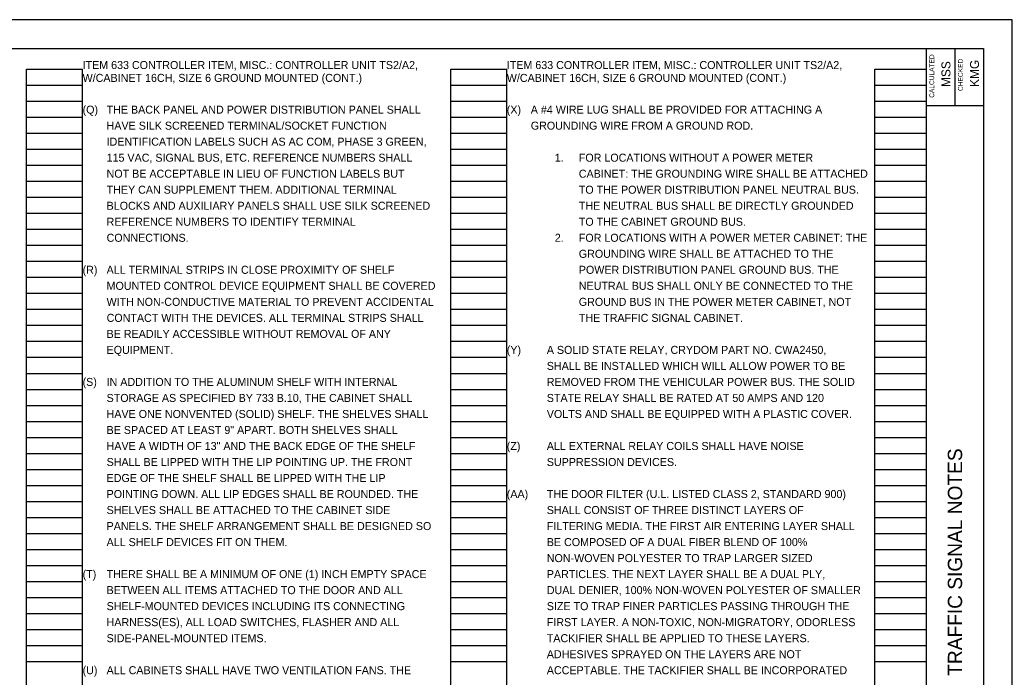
# Model space of a CAD drawing. Extents: x -38 to 65, y -51 to 25.
# Drawn here: x 16.14 to 33.49, y 3 to 14.49 of the extents above; entities that cross this region are included whole.
import ezdxf

# ---------------------------------------------------------------- set-up
doc = ezdxf.new("R2010")
doc.units = 0
for name, color, linetype in [('Level 63', 7, 'Continuous'), ('PF_P_Text', 7, 'Continuous'), ('SC_Scratch1', 7, 'Continuous'), ('SH_Cut_Line', 7, 'Continuous'), ('SH_Data', 7, 'Continuous'), ('SH_Text', 7, 'Continuous')]:
    doc.layers.add(name, color=color, linetype=linetype)

msp = doc.modelspace()

# ---------------------------------------------------------------- linework, layer by layer
at = {"layer": 'PF_P_Text'}
for p, q in [((31.994, -7.008), (31.994, 13.992)), ((32.494, 13.992), (32.494, 12.992)), ((31.994, 12.992), (32.994, 12.992))]:
    msp.add_line(p, q, dxfattribs=at)
msp.add_lwpolyline([(1.494, 13.992), (32.994, 13.992), (32.994, -7.008), (1.494, -7.008)], close=True, dxfattribs=at)
at = {"layer": 'SC_Scratch1'}
for p, q in [((16.254, -6.528), (16.254, 13.632)), ((16.254, 13.632), (17.234, 13.632)), ((17.234, -6.528), (17.234, 13.632)), ((23.674, -6.528), (23.674, 13.632)), ((23.674, 13.632), (24.654, 13.632)), ((24.654, -6.528), (24.654, 13.632)), ((31.094, -6.528), (31.094, 13.632)), ((31.094, 13.632), (31.994, 13.632)), ((31.994, -6.528), (31.994, 13.632)), ((16.254, 13.352), (17.234, 13.352)), ((23.674, 13.352), (24.654, 13.352)), ((31.094, 13.352), (31.994, 13.352)), ((16.254, 13.072), (17.234, 13.072)), ((23.674, 13.072), (24.654, 13.072)), ((31.094, 13.072), (31.994, 13.072)), ((16.254, 12.792), (17.234, 12.792)), ((23.674, 12.792), (24.654, 12.792)), ((31.094, 12.792), (31.994, 12.792)), ((16.254, 12.512), (17.234, 12.512)), ((23.674, 12.512), (24.654, 12.512)), ((31.094, 12.512), (31.994, 12.512)), ((16.254, 12.232), (17.234, 12.232)), ((23.674, 12.232), (24.654, 12.232)), ((31.094, 12.232), (31.994, 12.232)), ((16.254, 11.952), (17.234, 11.952)), ((23.674, 11.952), (24.654, 11.952)), ((31.094, 11.952), (31.994, 11.952)), ((16.254, 11.672), (17.234, 11.672)), ((23.674, 11.672), (24.654, 11.672)), ((31.094, 11.672), (31.994, 11.672)), ((16.254, 11.392), (17.234, 11.392)), ((23.674, 11.392), (24.654, 11.392)), ((31.094, 11.392), (31.994, 11.392)), ((16.254, 11.112), (17.234, 11.112)), ((23.674, 11.112), (24.654, 11.112)), ((31.094, 11.112), (31.994, 11.112)), ((16.254, 10.832), (17.234, 10.832)), ((23.674, 10.832), (24.654, 10.832)), ((31.094, 10.832), (31.994, 10.832)), ((16.254, 10.552), (17.234, 10.552)), ((23.674, 10.552), (24.654, 10.552)), ((31.094, 10.552), (31.994, 10.552)), ((16.254, 10.272), (17.234, 10.272)), ((23.674, 10.272), (24.654, 10.272)), ((31.094, 10.272), (31.994, 10.272)), ((16.254, 9.992), (17.234, 9.992)), ((23.674, 9.992), (24.654, 9.992)), ((31.094, 9.992), (31.994, 9.992)), ((16.254, 9.712), (17.234, 9.712)), ((23.674, 9.712), (24.654, 9.712)), ((31.094, 9.712), (31.994, 9.712)), ((16.254, 9.432), (17.234, 9.432)), ((23.674, 9.432), (24.654, 9.432)), ((31.094, 9.432), (31.994, 9.432)), ((16.254, 9.152), (17.234, 9.152)), ((23.674, 9.152), (24.654, 9.152)), ((31.094, 9.152), (31.994, 9.152)), ((16.254, 8.872), (17.234, 8.872)), ((23.674, 8.872), (24.654, 8.872)), ((31.094, 8.872), (31.994, 8.872)), ((16.254, 8.592), (17.234, 8.592)), ((23.674, 8.592), (24.654, 8.592)), ((31.094, 8.592), (31.994, 8.592)), ((16.254, 8.312), (17.234, 8.312)), ((23.674, 8.312), (24.654, 8.312)), ((31.094, 8.312), (31.994, 8.312)), ((16.254, 8.032), (17.234, 8.032)), ((23.674, 8.032), (24.654, 8.032)), ((31.094, 8.032), (31.994, 8.032)), ((16.254, 7.752), (17.234, 7.752)), ((23.674, 7.752), (24.654, 7.752)), ((31.094, 7.752), (31.994, 7.752)), ((16.254, 7.472), (17.234, 7.472)), ((23.674, 7.472), (24.654, 7.472)), ((31.094, 7.472), (31.994, 7.472)), ((16.254, 7.192), (17.234, 7.192)), ((23.674, 7.192), (24.654, 7.192)), ((31.094, 7.192), (31.994, 7.192)), ((16.254, 6.912), (17.234, 6.912)), ((23.674, 6.912), (24.654, 6.912)), ((31.094, 6.912), (31.994, 6.912)), ((16.254, 6.632), (17.234, 6.632)), ((23.674, 6.632), (24.654, 6.632)), ((31.094, 6.632), (31.994, 6.632)), ((16.254, 6.352), (17.234, 6.352)), ((23.674, 6.352), (24.654, 6.352)), ((31.094, 6.352), (31.994, 6.352)), ((16.254, 6.072), (17.234, 6.072)), ((23.674, 6.072), (24.654, 6.072)), ((31.094, 6.072), (31.994, 6.072)), ((16.254, 5.792), (17.234, 5.792)), ((23.674, 5.792), (24.654, 5.792)), ((31.094, 5.792), (31.994, 5.792)), ((16.254, 5.512), (17.234, 5.512)), ((23.674, 5.512), (24.654, 5.512)), ((31.094, 5.512), (31.994, 5.512)), ((16.254, 5.232), (17.234, 5.232)), ((23.674, 5.232), (24.654, 5.232)), ((31.094, 5.232), (31.994, 5.232)), ((16.254, 4.952), (17.234, 4.952)), ((23.674, 4.952), (24.654, 4.952)), ((31.094, 4.952), (31.994, 4.952)), ((16.254, 4.672), (17.234, 4.672)), ((23.674, 4.672), (24.654, 4.672)), ((31.094, 4.672), (31.994, 4.672)), ((16.254, 4.392), (17.234, 4.392)), ((23.674, 4.392), (24.654, 4.392)), ((31.094, 4.392), (31.994, 4.392)), ((16.254, 4.112), (17.234, 4.112)), ((23.674, 4.112), (24.654, 4.112)), ((31.094, 4.112), (31.994, 4.112)), ((16.254, 3.832), (17.234, 3.832)), ((23.674, 3.832), (24.654, 3.832)), ((31.094, 3.832), (31.994, 3.832)), ((16.254, 3.552), (17.234, 3.552)), ((23.674, 3.552), (24.654, 3.552)), ((31.094, 3.552), (31.994, 3.552)), ((16.254, 3.272), (17.234, 3.272)), ((23.674, 3.272), (24.654, 3.272)), ((31.094, 3.272), (31.994, 3.272))]:
    msp.add_line(p, q, dxfattribs=at)
at = {"layer": 'SH_Cut_Line'}
msp.add_lwpolyline([(-0.506, -7.508), (33.494, -7.508), (33.494, 14.492), (-0.506, 14.492)], close=True, dxfattribs=at)

# ---------------------------------------------------------------- texts
at = {"layer": 'Level 63'}
for s, p in [('CALCULATED', (32.13, 13.129)), ('CHECKED', (32.63, 13.248))]:
    msp.add_text(s, height=0.0833, rotation=90, dxfattribs=at).set_placement(p)
at = {"layer": 'SH_Data'}
for s, p in [('ITEM 633 CONTROLLER ITEM, MISC.: CONTROLLER UNIT TS2/A2, ', (17.234, 13.632)), ('ITEM 633 CONTROLLER ITEM, MISC.: CONTROLLER UNIT TS2/A2, ', (24.654, 13.632)), ('W/CABINET 16CH, SIZE 6 GROUND MOUNTED (CONT.)', (17.234, 13.407)), ('W/CABINET 16CH, SIZE 6 GROUND MOUNTED (CONT.)', (24.654, 13.407)), ('(Q)', (17.234, 12.852)), ('THE BACK PANEL AND POWER DISTRIBUTION PANEL SHALL ', (17.654, 12.852)), ('(X)', (24.654, 12.852)), ('A #4 WIRE LUG SHALL BE PROVIDED FOR ATTACHING A ', (25.074, 12.852)), ('HAVE SILK SCREENED TERMINAL/SOCKET FUNCTION ', (17.654, 12.572)), ('GROUNDING WIRE FROM A GROUND ROD.  ', (25.074, 12.572)), ('IDENTIFICATION LABELS SUCH AS AC COM, PHASE 3 GREEN, ', (17.654, 12.292)), ('115 VAC, SIGNAL BUS, ETC. REFERENCE NUMBERS SHALL ', (17.654, 12.012)), ('1.', (25.494, 12.012)), ('FOR LOCATIONS WITHOUT A POWER METER ', (25.914, 12.012)), ('NOT BE ACCEPTABLE IN LIEU OF FUNCTION LABELS BUT ', (17.654, 11.732)), ('CABINET: THE GROUNDING WIRE SHALL BE ATTACHED ', (25.914, 11.732)), ('THEY CAN SUPPLEMENT THEM. ADDITIONAL TERMINAL ', (17.654, 11.452)), ('TO THE POWER DISTRIBUTION PANEL NEUTRAL BUS. ', (25.914, 11.452)), ('BLOCKS AND AUXILIARY PANELS SHALL USE SILK SCREENED ', (17.654, 11.172)), ('THE NEUTRAL BUS SHALL BE DIRECTLY GROUNDED ', (25.914, 11.172)), ('REFERENCE NUMBERS TO IDENTIFY TERMINAL ', (17.654, 10.892)), ('TO THE CABINET GROUND BUS.', (25.914, 10.892)), ('CONNECTIONS.', (17.654, 10.612)), ('2.', (25.494, 10.612)), ('FOR LOCATIONS WITH A POWER METER CABINET: THE ', (25.914, 10.612)), ('GROUNDING WIRE SHALL BE ATTACHED TO THE ', (25.914, 10.332)), ('(R)', (17.234, 10.052)), ('ALL TERMINAL STRIPS IN CLOSE PROXIMITY OF SHELF ', (17.654, 10.052)), ('POWER DISTRIBUTION PANEL GROUND BUS. THE ', (25.914, 10.052)), ('MOUNTED CONTROL DEVICE EQUIPMENT SHALL BE COVERED ', (17.654, 9.772)), ('NEUTRAL BUS SHALL ONLY BE CONNECTED TO THE ', (25.914, 9.772)), ('WITH NON-CONDUCTIVE MATERIAL TO PREVENT ACCIDENTAL ', (17.654, 9.492)), ('GROUND BUS IN THE POWER METER CABINET, NOT ', (25.914, 9.492)), ('CONTACT WITH THE DEVICES. ALL TERMINAL STRIPS SHALL ', (17.654, 9.212)), ('THE TRAFFIC SIGNAL CABINET.', (25.914, 9.212)), ('BE READILY ACCESSIBLE WITHOUT REMOVAL OF ANY ', (17.654, 8.932)), ('EQUIPMENT.', (17.654, 8.652)), ('(Y)', (24.654, 8.652)), ('A SOLID STATE RELAY, CRYDOM PART NO. CWA2450, ', (25.354, 8.652)), ('SHALL BE INSTALLED WHICH WILL ALLOW POWER TO BE ', (25.354, 8.372)), ('(S)', (17.234, 8.092)), ('IN ADDITION TO THE ALUMINUM SHELF WITH INTERNAL ', (17.654, 8.092)), ('REMOVED FROM THE VEHICULAR POWER BUS. THE SOLID ', (25.354, 8.092)), ('STORAGE AS SPECIFIED BY 733 B.10, THE CABINET SHALL ', (17.654, 7.812)), ('STATE RELAY SHALL BE RATED AT 50 AMPS AND 120 ', (25.354, 7.812)), ('HAVE ONE NONVENTED (SOLID) SHELF. THE SHELVES SHALL ', (17.654, 7.532)), ('VOLTS AND SHALL BE EQUIPPED WITH A PLASTIC COVER.', (25.354, 7.532)), ('BE SPACED AT LEAST 9" APART. BOTH SHELVES SHALL ', (17.654, 7.252)), ('(Z)', (24.654, 6.972)), ('HAVE A WIDTH OF 13" AND THE BACK EDGE OF THE SHELF ', (17.654, 6.972)), ('ALL EXTERNAL RELAY COILS SHALL HAVE NOISE ', (25.354, 6.972)), ('SHALL BE LIPPED WITH THE LIP POINTING UP. THE FRONT ', (17.654, 6.692)), ('SUPPRESSION DEVICES. ', (25.354, 6.692)), ('EDGE OF THE SHELF SHALL BE LIPPED WITH THE LIP ', (17.654, 6.412)), ('POINTING DOWN. ALL LIP EDGES SHALL BE ROUNDED. THE ', (17.654, 6.132)), ('(AA)', (24.654, 6.132)), ('THE DOOR FILTER (U.L. LISTED CLASS 2, STANDARD 900) ', (25.354, 6.132)), ('SHELVES SHALL BE ATTACHED TO THE CABINET SIDE ', (17.654, 5.852)), ('SHALL CONSIST OF THREE DISTINCT LAYERS OF ', (25.354, 5.852)), ('PANELS. THE SHELF ARRANGEMENT SHALL BE DESIGNED SO ', (17.654, 5.572)), ('FILTERING MEDIA. THE FIRST AIR ENTERING LAYER SHALL ', (25.354, 5.572)), ('ALL SHELF DEVICES FIT ON THEM.', (17.654, 5.292)), ('BE COMPOSED OF A DUAL FIBER BLEND OF 100% ', (25.354, 5.292)), ('NON-WOVEN POLYESTER TO TRAP LARGER SIZED ', (25.354, 5.012)), ('(T)', (17.234, 4.732)), ('THERE SHALL BE A MINIMUM OF ONE (1) INCH EMPTY SPACE ', (17.654, 4.732)), ('PARTICLES. THE NEXT LAYER SHALL BE A DUAL PLY, ', (25.354, 4.732)), ('BETWEEN ALL ITEMS ATTACHED TO THE DOOR AND ALL ', (17.654, 4.452)), ('DUAL DENIER, 100% NON-WOVEN POLYESTER OF SMALLER ', (25.354, 4.452)), ('SHELF-MOUNTED DEVICES INCLUDING ITS CONNECTING ', (17.654, 4.172)), ('SIZE TO TRAP FINER PARTICLES PASSING THROUGH THE ', (25.354, 4.172)), ('HARNESS(ES), ALL LOAD SWITCHES, FLASHER AND ALL ', (17.654, 3.892)), ('FIRST LAYER. A NON-TOXIC, NON-MIGRATORY, ODORLESS ', (25.354, 3.892)), ('SIDE-PANEL-MOUNTED ITEMS.', (17.654, 3.612)), ('TACKIFIER SHALL BE APPLIED TO THESE LAYERS. ', (25.354, 3.612)), ('ADHESIVES SPRAYED ON THE LAYERS ARE NOT ', (25.354, 3.332)), ('(U)', (17.234, 3.052)), ('ALL CABINETS SHALL HAVE TWO VENTILATION FANS. THE ', (17.654, 3.052)), ('ACCEPTABLE. THE TACKIFIER SHALL BE INCORPORATED ', (25.354, 3.052))]:
    msp.add_text(s, height=0.14, dxfattribs=at).set_placement(p)
at = {"layer": 'SH_Text'}
for s, height, p in [('MSS', 0.156, (32.414, 13.317)), ('KMG', 0.156, (32.914, 13.319)), ('TRAFFIC SIGNAL NOTES', 0.25, (32.619, 3.025))]:
    msp.add_text(s, height=height, rotation=90, dxfattribs=at).set_placement(p)

doc.saveas('drawing.dxf')
